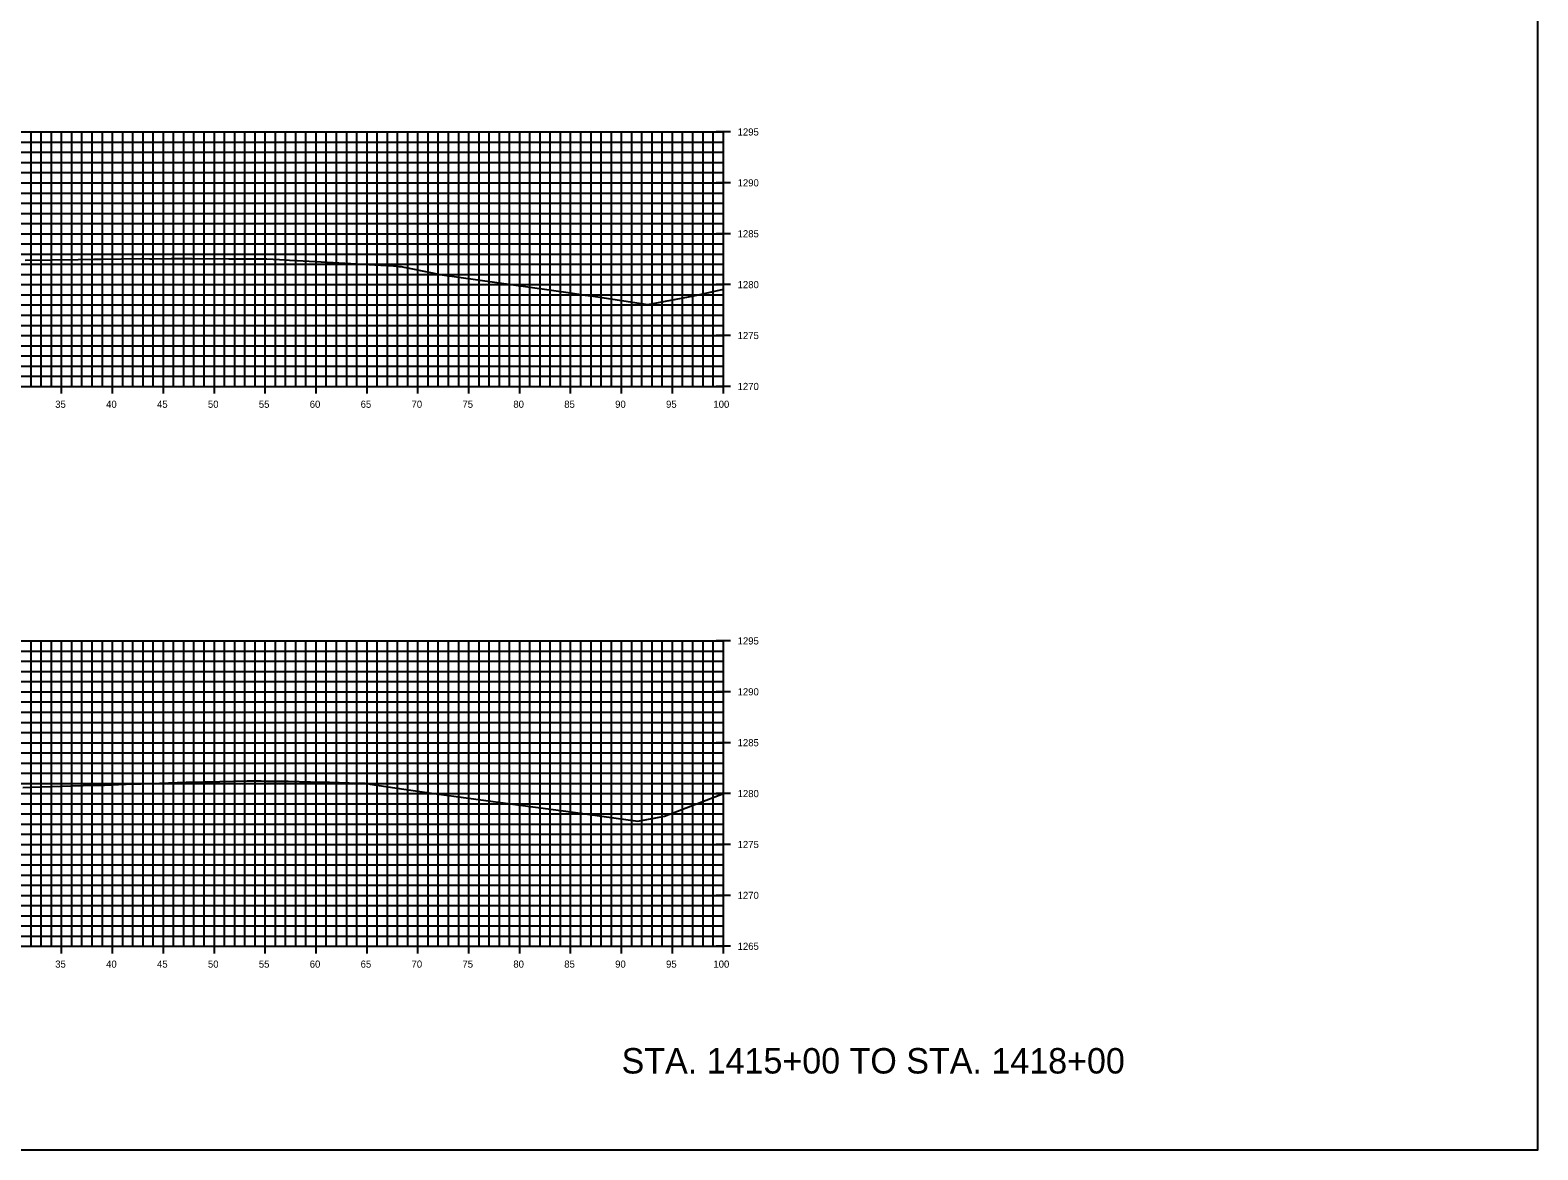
# Model space of a CAD drawing. Extents: x 674939 to 678919, y 750652 to 765176.
# Drawn here: x 678770.4 to 678918.5, y 757362.6 to 757472.6 of the extents above; entities that cross this region are included whole.
import ezdxf

# ---------------------------------------------------------------- set-up
doc = ezdxf.new("R2010")
doc.units = 0
for name, color, linetype in [('Level 10', 7, 'Continuous'), ('Level 20', 7, 'Continuous'), ('Level 21', 7, 'Continuous'), ('Level 4', 7, 'Continuous'), ('Level 8', 7, 'Continuous'), ('Level 9', 7, 'Continuous')]:
    doc.layers.add(name, color=color, linetype=linetype)

msp = doc.modelspace()

# ---------------------------------------------------------------- linework, layer by layer
at = {"layer": 'Level 10'}
for points in [[(678769.95, 757449.94), (678775.16, 757450.02), (678776.69, 757450.04), (678777.39, 757450.04), (678781.38, 757450.11), (678781.49, 757450.11), (678782.18, 757450.09), (678782.39, 757450.09), (678784.3, 757450.12), (678785.51, 757450.11), (678786.32, 757450.11), (678789.95, 757450.1), (678793.05, 757450.08), (678793.69, 757450.07), (678795.54, 757449.98), (678795.92, 757449.96), (678796.65, 757449.93), (678804.89, 757449.46), (678806.12, 757449.39), (678806.64, 757449.34), (678806.86, 757449.32), (678806.89, 757449.32), (678806.89, 757449.32), (678807.14, 757449.27), (678807.34, 757449.23), (678809.92, 757448.71), (678810.69, 757448.56), (678823.3, 757446.79), (678824.96, 757446.52), (678825.54, 757446.46), (678831.12, 757445.6), (678835.64, 757446.44), (678835.92, 757446.5), (678836.8, 757446.72), (678838.53, 757447.12)], [(678769.71, 757398.16), (678771.46, 757398.21), (678775.66, 757398.34), (678777.52, 757398.39), (678777.73, 757398.38), (678778.38, 757398.42), (678779.88, 757398.49), (678780.72, 757398.5), (678781.14, 757398.51), (678781.33, 757398.51), (678782.27, 757398.55), (678785.77, 757398.67), (678789.07, 757398.74), (678791.76, 757398.79), (678793.03, 757398.8), (678793.09, 757398.8), (678793.13, 757398.8), (678793.66, 757398.78), (678794.42, 757398.77), (678795.78, 757398.76), (678797.98, 757398.72), (678799.85, 757398.67), (678801.77, 757398.61), (678803.33, 757398.56), (678803.54, 757398.53), (678803.85, 757398.47), (678807.13, 757397.99), (678809.62, 757397.63), (678818.33, 757396.45), (678823.55, 757395.75), (678827.99, 757395.14), (678830.13, 757394.84), (678831.91, 757395.18), (678832.74, 757395.32), (678838.53, 757397.55)]]:
    msp.add_lwpolyline(points, dxfattribs=at)
at = {"layer": 'Level 20'}
for p, q in [((678638.53, 757462.55), (678838.53, 757462.55)), ((678770.53, 757437.55), (678770.53, 757462.55)), ((678771.53, 757437.55), (678771.53, 757462.55)), ((678772.53, 757437.55), (678772.53, 757462.55)), ((678773.53, 757437.55), (678773.53, 757462.55)), ((678774.53, 757437.55), (678774.53, 757462.55)), ((678775.53, 757437.55), (678775.53, 757462.55)), ((678776.53, 757437.55), (678776.53, 757462.55)), ((678777.53, 757437.55), (678777.53, 757462.55)), ((678778.53, 757437.55), (678778.53, 757462.55)), ((678779.53, 757437.55), (678779.53, 757462.55)), ((678780.53, 757437.55), (678780.53, 757462.55)), ((678781.53, 757437.55), (678781.53, 757462.55)), ((678782.53, 757437.55), (678782.53, 757462.55)), ((678783.53, 757437.55), (678783.53, 757462.55)), ((678784.53, 757437.55), (678784.53, 757462.55)), ((678785.53, 757437.55), (678785.53, 757462.55)), ((678786.53, 757437.55), (678786.53, 757462.55)), ((678787.53, 757437.55), (678787.53, 757462.55)), ((678788.53, 757437.55), (678788.53, 757462.55)), ((678789.53, 757437.55), (678789.53, 757462.55)), ((678790.53, 757437.55), (678790.53, 757462.55)), ((678791.53, 757437.55), (678791.53, 757462.55)), ((678792.53, 757437.55), (678792.53, 757462.55)), ((678793.53, 757437.55), (678793.53, 757462.55)), ((678794.53, 757437.55), (678794.53, 757462.55)), ((678795.53, 757437.55), (678795.53, 757462.55)), ((678796.53, 757437.55), (678796.53, 757462.55)), ((678797.53, 757437.55), (678797.53, 757462.55)), ((678798.53, 757437.55), (678798.53, 757462.55)), ((678799.53, 757437.55), (678799.53, 757462.55)), ((678800.53, 757437.55), (678800.53, 757462.55)), ((678801.53, 757437.55), (678801.53, 757462.55)), ((678802.53, 757437.55), (678802.53, 757462.55)), ((678803.53, 757437.55), (678803.53, 757462.55)), ((678804.53, 757437.55), (678804.53, 757462.55)), ((678805.53, 757437.55), (678805.53, 757462.55)), ((678806.53, 757437.55), (678806.53, 757462.55)), ((678807.53, 757437.55), (678807.53, 757462.55)), ((678808.53, 757437.55), (678808.53, 757462.55)), ((678809.53, 757437.55), (678809.53, 757462.55)), ((678810.53, 757437.55), (678810.53, 757462.55)), ((678811.53, 757437.55), (678811.53, 757462.55)), ((678812.53, 757437.55), (678812.53, 757462.55)), ((678813.53, 757437.55), (678813.53, 757462.55)), ((678814.53, 757437.55), (678814.53, 757462.55)), ((678815.53, 757437.55), (678815.53, 757462.55)), ((678816.53, 757437.55), (678816.53, 757462.55)), ((678817.53, 757437.55), (678817.53, 757462.55)), ((678818.53, 757437.55), (678818.53, 757462.55)), ((678819.53, 757437.55), (678819.53, 757462.55)), ((678820.53, 757437.55), (678820.53, 757462.55)), ((678821.53, 757437.55), (678821.53, 757462.55)), ((678822.53, 757437.55), (678822.53, 757462.55)), ((678823.53, 757437.55), (678823.53, 757462.55)), ((678824.53, 757437.55), (678824.53, 757462.55)), ((678825.53, 757437.55), (678825.53, 757462.55)), ((678826.53, 757437.55), (678826.53, 757462.55)), ((678827.53, 757437.55), (678827.53, 757462.55)), ((678828.53, 757437.55), (678828.53, 757462.55)), ((678829.53, 757437.55), (678829.53, 757462.55)), ((678830.53, 757437.55), (678830.53, 757462.55)), ((678831.53, 757437.55), (678831.53, 757462.55)), ((678832.53, 757437.55), (678832.53, 757462.55)), ((678833.53, 757437.55), (678833.53, 757462.55)), ((678834.53, 757437.55), (678834.53, 757462.55)), ((678835.53, 757437.55), (678835.53, 757462.55)), ((678836.53, 757437.55), (678836.53, 757462.55)), ((678837.53, 757437.55), (678837.53, 757462.55)), ((678838.53, 757437.55), (678838.53, 757462.55)), ((678638.53, 757461.55), (678838.53, 757461.55)), ((678638.53, 757460.55), (678838.53, 757460.55)), ((678638.53, 757459.55), (678838.53, 757459.55)), ((678638.53, 757458.55), (678838.53, 757458.55)), ((678638.53, 757457.55), (678838.53, 757457.55)), ((678638.53, 757456.55), (678838.53, 757456.55)), ((678638.53, 757455.55), (678838.53, 757455.55)), ((678638.53, 757454.55), (678838.53, 757454.55)), ((678638.53, 757453.55), (678838.53, 757453.55)), ((678638.53, 757452.55), (678838.53, 757452.55)), ((678638.53, 757451.55), (678838.53, 757451.55)), ((678638.53, 757450.55), (678838.53, 757450.55)), ((678638.53, 757449.55), (678838.53, 757449.55)), ((678638.53, 757448.55), (678838.53, 757448.55)), ((678638.53, 757447.55), (678838.53, 757447.55)), ((678638.53, 757446.55), (678838.53, 757446.55)), ((678638.53, 757445.55), (678838.53, 757445.55)), ((678638.53, 757444.55), (678838.53, 757444.55)), ((678638.53, 757443.55), (678838.53, 757443.55)), ((678638.53, 757442.55), (678838.53, 757442.55)), ((678638.53, 757441.55), (678838.53, 757441.55)), ((678638.53, 757440.55), (678838.53, 757440.55)), ((678638.53, 757439.55), (678838.53, 757439.55)), ((678638.53, 757438.55), (678838.53, 757438.55)), ((678638.53, 757437.55), (678838.53, 757437.55)), ((678638.53, 757412.55), (678838.53, 757412.55)), ((678770.53, 757382.55), (678770.53, 757412.55)), ((678771.53, 757382.55), (678771.53, 757412.55)), ((678772.53, 757382.55), (678772.53, 757412.55)), ((678773.53, 757382.55), (678773.53, 757412.55)), ((678774.53, 757382.55), (678774.53, 757412.55)), ((678775.53, 757382.55), (678775.53, 757412.55)), ((678776.53, 757382.55), (678776.53, 757412.55)), ((678777.53, 757382.55), (678777.53, 757412.55)), ((678778.53, 757382.55), (678778.53, 757412.55)), ((678779.53, 757382.55), (678779.53, 757412.55)), ((678780.53, 757382.55), (678780.53, 757412.55)), ((678781.53, 757382.55), (678781.53, 757412.55)), ((678782.53, 757382.55), (678782.53, 757412.55)), ((678783.53, 757382.55), (678783.53, 757412.55)), ((678784.53, 757382.55), (678784.53, 757412.55)), ((678785.53, 757382.55), (678785.53, 757412.55)), ((678786.53, 757382.55), (678786.53, 757412.55)), ((678787.53, 757382.55), (678787.53, 757412.55)), ((678788.53, 757382.55), (678788.53, 757412.55)), ((678789.53, 757382.55), (678789.53, 757412.55)), ((678790.53, 757382.55), (678790.53, 757412.55)), ((678791.53, 757382.55), (678791.53, 757412.55)), ((678792.53, 757382.55), (678792.53, 757412.55)), ((678793.53, 757382.55), (678793.53, 757412.55)), ((678794.53, 757382.55), (678794.53, 757412.55)), ((678795.53, 757382.55), (678795.53, 757412.55)), ((678796.53, 757382.55), (678796.53, 757412.55)), ((678797.53, 757382.55), (678797.53, 757412.55)), ((678798.53, 757382.55), (678798.53, 757412.55)), ((678799.53, 757382.55), (678799.53, 757412.55)), ((678800.53, 757382.55), (678800.53, 757412.55)), ((678801.53, 757382.55), (678801.53, 757412.55)), ((678802.53, 757382.55), (678802.53, 757412.55)), ((678803.53, 757382.55), (678803.53, 757412.55)), ((678804.53, 757382.55), (678804.53, 757412.55)), ((678805.53, 757382.55), (678805.53, 757412.55)), ((678806.53, 757382.55), (678806.53, 757412.55)), ((678807.53, 757382.55), (678807.53, 757412.55)), ((678808.53, 757382.55), (678808.53, 757412.55)), ((678809.53, 757382.55), (678809.53, 757412.55)), ((678810.53, 757382.55), (678810.53, 757412.55)), ((678811.53, 757382.55), (678811.53, 757412.55)), ((678812.53, 757382.55), (678812.53, 757412.55)), ((678813.53, 757382.55), (678813.53, 757412.55)), ((678814.53, 757382.55), (678814.53, 757412.55)), ((678815.53, 757382.55), (678815.53, 757412.55)), ((678816.53, 757382.55), (678816.53, 757412.55)), ((678817.53, 757382.55), (678817.53, 757412.55)), ((678818.53, 757382.55), (678818.53, 757412.55)), ((678819.53, 757382.55), (678819.53, 757412.55)), ((678820.53, 757382.55), (678820.53, 757412.55)), ((678821.53, 757382.55), (678821.53, 757412.55)), ((678822.53, 757382.55), (678822.53, 757412.55)), ((678823.53, 757382.55), (678823.53, 757412.55)), ((678824.53, 757382.55), (678824.53, 757412.55)), ((678825.53, 757382.55), (678825.53, 757412.55)), ((678826.53, 757382.55), (678826.53, 757412.55)), ((678827.53, 757382.55), (678827.53, 757412.55)), ((678828.53, 757382.55), (678828.53, 757412.55)), ((678829.53, 757382.55), (678829.53, 757412.55)), ((678830.53, 757382.55), (678830.53, 757412.55)), ((678831.53, 757382.55), (678831.53, 757412.55)), ((678832.53, 757382.55), (678832.53, 757412.55)), ((678833.53, 757382.55), (678833.53, 757412.55)), ((678834.53, 757382.55), (678834.53, 757412.55)), ((678835.53, 757382.55), (678835.53, 757412.55)), ((678836.53, 757382.55), (678836.53, 757412.55)), ((678837.53, 757382.55), (678837.53, 757412.55)), ((678838.53, 757382.55), (678838.53, 757412.55)), ((678638.53, 757411.55), (678838.53, 757411.55)), ((678638.53, 757410.55), (678838.53, 757410.55)), ((678638.53, 757409.55), (678838.53, 757409.55)), ((678638.53, 757408.55), (678838.53, 757408.55)), ((678638.53, 757407.55), (678838.53, 757407.55)), ((678638.53, 757406.55), (678838.53, 757406.55)), ((678638.53, 757405.55), (678838.53, 757405.55)), ((678638.53, 757404.55), (678838.53, 757404.55)), ((678638.53, 757403.55), (678838.53, 757403.55)), ((678638.53, 757402.55), (678838.53, 757402.55)), ((678638.53, 757401.55), (678838.53, 757401.55)), ((678638.53, 757400.55), (678838.53, 757400.55)), ((678638.53, 757399.55), (678838.53, 757399.55)), ((678638.53, 757398.55), (678838.53, 757398.55)), ((678638.53, 757397.55), (678838.53, 757397.55)), ((678638.53, 757396.55), (678838.53, 757396.55)), ((678638.53, 757395.55), (678838.53, 757395.55)), ((678638.53, 757394.55), (678838.53, 757394.55)), ((678638.53, 757393.55), (678838.53, 757393.55)), ((678638.53, 757392.55), (678838.53, 757392.55)), ((678638.53, 757391.55), (678838.53, 757391.55)), ((678638.53, 757390.55), (678838.53, 757390.55)), ((678638.53, 757389.55), (678838.53, 757389.55)), ((678638.53, 757388.55), (678838.53, 757388.55)), ((678638.53, 757387.55), (678838.53, 757387.55)), ((678638.53, 757386.55), (678838.53, 757386.55)), ((678638.53, 757385.55), (678838.53, 757385.55)), ((678638.53, 757384.55), (678838.53, 757384.55)), ((678638.53, 757383.55), (678838.53, 757383.55)), ((678638.53, 757382.55), (678838.53, 757382.55))]:
    msp.add_line(p, q, dxfattribs=at)
at = {"layer": 'Level 4'}
msp.add_lwpolyline([(678578.53, 757362.55), (678918.53, 757362.55), (678918.53, 757582.55), (678578.53, 757582.55)], close=True, dxfattribs=at)
at = {"layer": 'Level 8'}
for p, q in [((678839.23, 757462.55), (678837.83, 757462.55)), ((678838.53, 757437.55), (678838.53, 757462.55)), ((678839.23, 757457.55), (678837.83, 757457.55)), ((678839.23, 757452.55), (678837.83, 757452.55)), ((678839.23, 757447.55), (678837.83, 757447.55)), ((678839.23, 757442.55), (678837.83, 757442.55)), ((678773.53, 757436.85), (678773.53, 757438.25)), ((678778.53, 757436.85), (678778.53, 757438.25)), ((678783.53, 757436.85), (678783.53, 757438.25)), ((678788.53, 757436.85), (678788.53, 757438.25)), ((678793.53, 757436.85), (678793.53, 757438.25)), ((678798.53, 757436.85), (678798.53, 757438.25)), ((678803.53, 757436.85), (678803.53, 757438.25)), ((678808.53, 757436.85), (678808.53, 757438.25)), ((678813.53, 757436.85), (678813.53, 757438.25)), ((678818.53, 757436.85), (678818.53, 757438.25)), ((678823.53, 757436.85), (678823.53, 757438.25)), ((678828.53, 757436.85), (678828.53, 757438.25)), ((678833.53, 757436.85), (678833.53, 757438.25)), ((678838.53, 757436.85), (678838.53, 757438.25)), ((678638.53, 757437.55), (678838.53, 757437.55)), ((678839.23, 757437.55), (678837.83, 757437.55)), ((678839.23, 757412.55), (678837.83, 757412.55)), ((678838.53, 757382.55), (678838.53, 757412.55)), ((678839.23, 757407.55), (678837.83, 757407.55)), ((678839.23, 757402.55), (678837.83, 757402.55)), ((678839.23, 757397.55), (678837.83, 757397.55)), ((678839.23, 757392.55), (678837.83, 757392.55)), ((678839.23, 757387.55), (678837.83, 757387.55)), ((678638.53, 757382.55), (678838.53, 757382.55)), ((678773.53, 757381.85), (678773.53, 757383.25)), ((678778.53, 757381.85), (678778.53, 757383.25)), ((678783.53, 757381.85), (678783.53, 757383.25)), ((678788.53, 757381.85), (678788.53, 757383.25)), ((678793.53, 757381.85), (678793.53, 757383.25)), ((678798.53, 757381.85), (678798.53, 757383.25)), ((678803.53, 757381.85), (678803.53, 757383.25)), ((678808.53, 757381.85), (678808.53, 757383.25)), ((678813.53, 757381.85), (678813.53, 757383.25)), ((678818.53, 757381.85), (678818.53, 757383.25)), ((678823.53, 757381.85), (678823.53, 757383.25)), ((678828.53, 757381.85), (678828.53, 757383.25)), ((678833.53, 757381.85), (678833.53, 757383.25)), ((678839.23, 757382.55), (678837.83, 757382.55)), ((678838.53, 757381.85), (678838.53, 757383.25))]:
    msp.add_line(p, q, dxfattribs=at)

# ---------------------------------------------------------------- texts
at = {"layer": 'Level 21'}
msp.add_text('STA. 1415+00 TO STA. 1418+00', height=2.5, dxfattribs=at).set_placement((678828.53, 757370.05))
at = {"layer": 'Level 9'}
for s, p in [('1295', (678839.93, 757462.2)), ('1290', (678839.93, 757457.2)), ('1285', (678839.93, 757452.2)), ('1280', (678839.93, 757447.2)), ('1275', (678839.93, 757442.2)), ('1270', (678839.93, 757437.2)), ('35', (678772.9, 757435.45)), ('40', (678777.9, 757435.45)), ('45', (678782.9, 757435.45)), ('50', (678787.9, 757435.45)), ('55', (678792.9, 757435.45)), ('60', (678797.9, 757435.45)), ('65', (678802.9, 757435.45)), ('70', (678807.9, 757435.45)), ('75', (678812.9, 757435.45)), ('80', (678817.9, 757435.45)), ('85', (678822.9, 757435.45)), ('90', (678827.9, 757435.45)), ('95', (678832.9, 757435.45)), ('100', (678837.55, 757435.45)), ('1295', (678839.93, 757412.2)), ('1290', (678839.93, 757407.2)), ('1285', (678839.93, 757402.2)), ('1280', (678839.93, 757397.2)), ('1275', (678839.93, 757392.2)), ('1270', (678839.93, 757387.2)), ('1265', (678839.93, 757382.2)), ('35', (678772.9, 757380.45)), ('40', (678777.9, 757380.45)), ('45', (678782.9, 757380.45)), ('50', (678787.9, 757380.45)), ('55', (678792.9, 757380.45)), ('60', (678797.9, 757380.45)), ('65', (678802.9, 757380.45)), ('70', (678807.9, 757380.45)), ('75', (678812.9, 757380.45)), ('80', (678817.9, 757380.45)), ('85', (678822.9, 757380.45)), ('90', (678827.9, 757380.45)), ('95', (678832.9, 757380.45)), ('100', (678837.55, 757380.45))]:
    msp.add_text(s, height=0.7, dxfattribs=at).set_placement(p)

doc.saveas('drawing.dxf')
